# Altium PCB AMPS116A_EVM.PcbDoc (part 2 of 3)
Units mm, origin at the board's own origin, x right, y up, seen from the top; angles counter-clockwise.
Board outline 95 x 85 mm, 4 copper layers (Top Layer, Mid-Layer 1, Mid-Layer 2, Bottom Layer), stack 1.554 mm thick; 252 components, 134 nets, 806 pads, 625 vias.
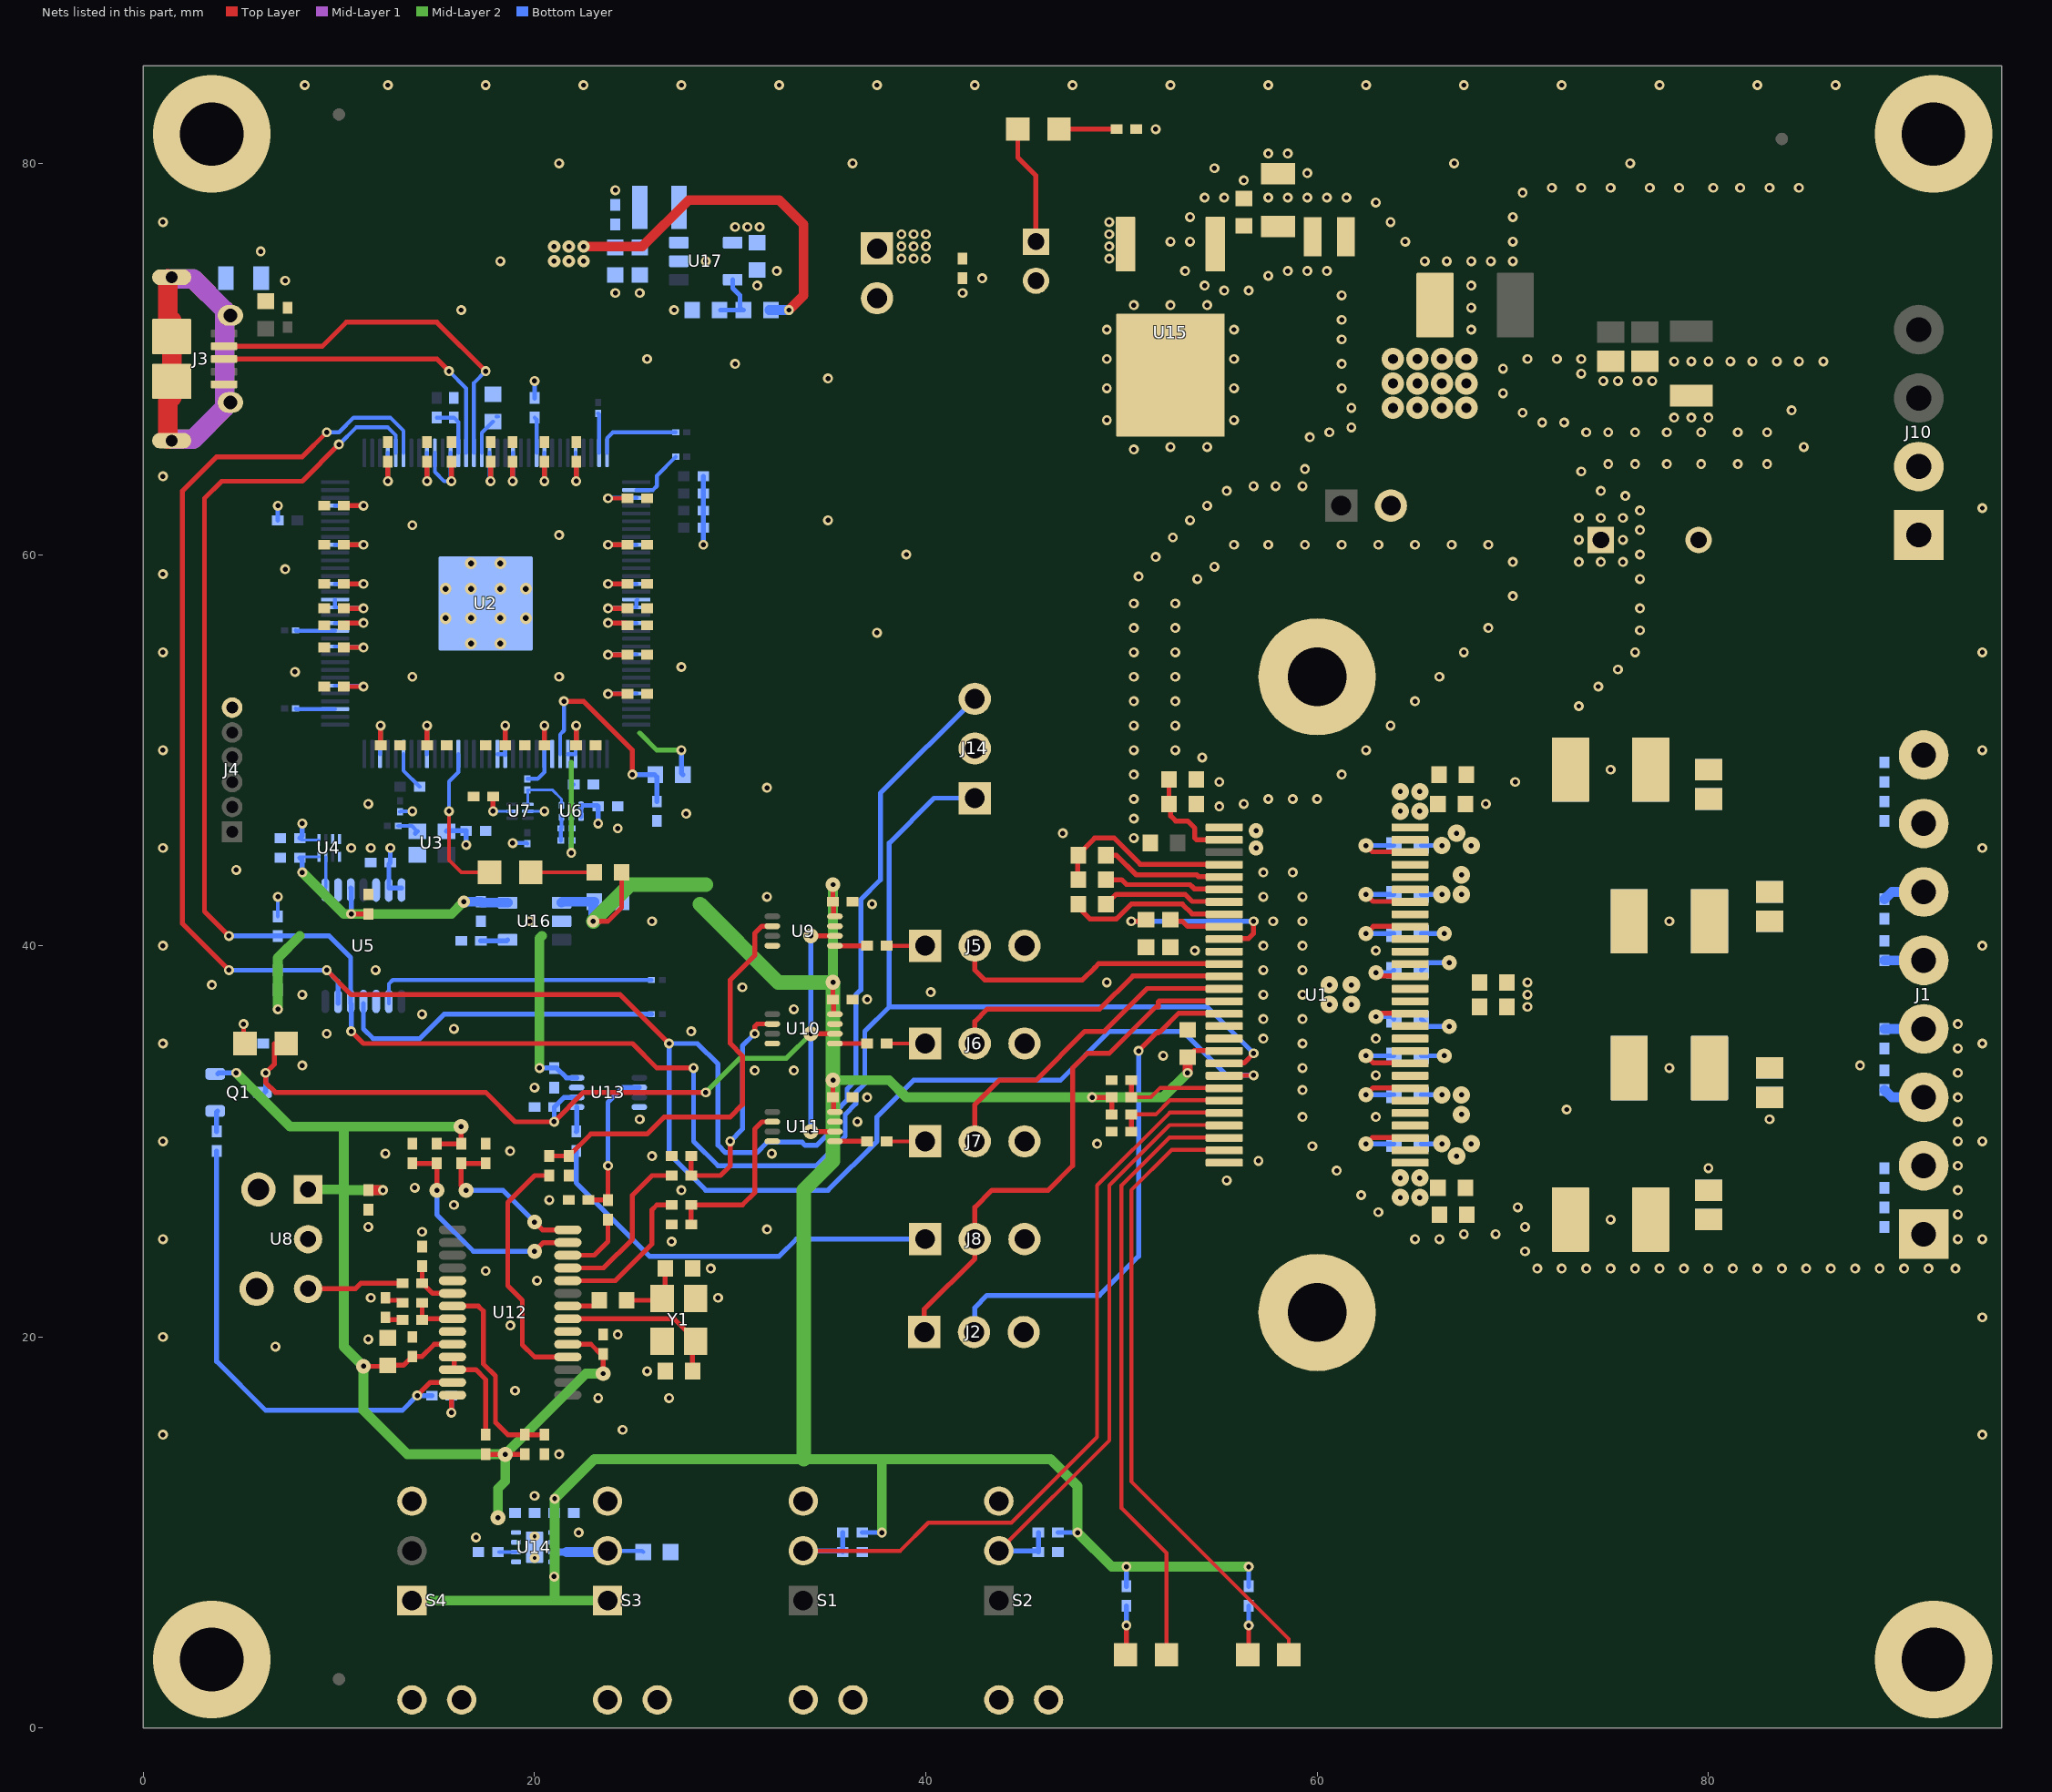
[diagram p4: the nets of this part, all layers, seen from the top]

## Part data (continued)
D2: library part CMP-0002829-3, "LED, Red, SMD", Color=red, Manufacturer=Lite-On, PartNumber=LTST-C170KRKT, Value1=W, Value2=2V
D3 D4: library part CMP-0002889-2, "LED, Blue, SMD", Color=Blue, Manufacturer=Lite-On, PartNumber=LTST-C170TBKT, Value1=W, Value2=3.3V
D5: library part CMP-0002888-2, "LED, Green, SMD", Color=Green, Manufacturer=Lite-On, PartNumber=LTST-C170KGKT, Value1=W, Value2=2V
FID1 FID2 FID3 FID4 FID5 FID6: library part CMP-0077181-1, "Fiducial mark.  There is nothing to buy or mount.", Manufacturer=N/A
H1: library part CMP-0004050-1, "Heat Sink for DKQ Packages, 41.4x20 mm", Manufacturer=Any, PartNumber=HS-DKQ56_20X41.4X32.77
H6 H7 H8 H9: library part CMP-0003665-1, "Standoff, Hex, 12mm, M3, Aluminum", Manufacturer=Keystone, PartNumber=24434, Supplier Part Number 1=36-24434-ND
J1: library part CMP-0075135-1, "Terminal Block, 3.5mm, 8-Pos, TH", Color=Grey, Manufacturer="On-Shore Technology", PartNumber=ED555/8DS, Supplier Part Number 1=ED1520-ND
J2 J5 J6 J7 J8 J14: library part CMP-0002334-1, "Header, 100mil, 3x1, Gold, TH", Manufacturer="Sullins Connector Solutions", PartNumber=PBC03SAAN, Supplier Part Number 1=S1011E-03-ND
J3: library part CMP-0055301-1, "Connector, Receptacle, Micro-USB Type AB, R/A, Bottom Mount SMT", Manufacturer=Molex, Supplier Part Number 1=WM17143CT-ND
J4: library part CMP-0054640-1, "Receptacle, 50mil, 6x1, Gold, R/A, TH", Color=Black, Manufacturer="Sullins Connector Solutions", PartNumber=LPPB061NGCN-RC, Supplier Part Number 1=S9010E-06-ND
J10: library part CMP-0074917-1, "Terminal Block, 3.5mm Pitch, 4x1, TH", Color=Grey, Current_A=6A, Manufacturer="On-Shore Technology", PartNumber=ED555/4DS, Supplier Part Number 1=ED1516-ND, Voltage_V=150V
J12 J13: library part CMP-0054566-1, "Header, 100mil, 2x1, Gold, TH", Color=Black, Current_A=3A, Manufacturer="Sullins Connector Solutions", PartNumber=PBC02SAAN, Supplier Part Number 1=S1011E-02-ND, Voltage_V=1.8kV
L1 L2 L7 L8 L9 L10 L11 L12: library part CMP-0059924-1, "Inductor, 3.3 uH, 4.5 A, 0.038 ohm, AEC-Q200 Grade 0, SMD", Manufacturer=Cyntec, Value1="0.038 ohm", Value2=4.5A, ValueDisplayed=3.3uH
L3: library part CMP-0003428-2, "Ferrite Bead, 30 ohm @ 100 MHz, 6 A, 0805", Manufacturer=TDK, Supplier Part Number 1=445-1566-1-ND, Value1="0.01 ohm", Value2=6A, ValueDisplayed="30 ohm"
L4: library part CMP-0059922-1, "Inductor, 1.5 uH, 5.5 A, 0.017 ohm, AEC-Q200 Grade 0, SMD", Manufacturer=Cyntec, Value1="0.017 ohm", Value2=5.5A, ValueDisplayed=1.5uH
L5: library part CMP-0003430-1, "Ferrite Bead, 180 ohm @ 100 MHz, 3.4 A, 0806", Manufacturer=MuRata, PartNumber=NFZ2MSM181SN10L, Supplier Part Number 1=81-NFZ2MSM181SN10L, Value1="0.025 ohm", Value2=3.4A, ValueDisplayed="180 ohm"
L6: library part CMP-0058752-1, "Inductor, Multilayer, Ferrite, 2.2 uH, 1.3 A, 0.08 ohm, SMD", Manufacturer=MuRata, Supplier Part Number 1=490-5114-1-ND, Value1="0.08 ohm", Value2=1.3A, ValueDisplayed=2.2uH
Logo1: library part CMP-0074838-1, "Texas Instrument Corporate Signature"
Logo2: library part CMP-0074847-1, "FCC_disclaimer"
Logo3: library part CMP-0074769-1
Logo4: library part CMP-0074844-1
Q1: library part CMP-0000326-2, "Transistor, PNP, 40 V, 0.2 A, SOT-23", Manufacturer="Diodes Inc.", Supplier Part Number 1=MMBT3906-FDICT-ND, Value1="0.2 A", Value2=400
R2 R3 R4 R5 R7 R9 R46 R48 R52 R53 R55 R56: library part CMP-0026414-2, "RES, 4.99 k, 1%, 0.063 W, AEC-Q200 Grade 0, 0402", Manufacturer=Vishay-Dale, PartNumber=CRCW04024K99FKED, Power_W=63mW, Supplier Part Number 1=541-4.99KLCT-ND, TempCo="100 ppm/C", Tolerance_%=1%, Value2=0.063W, Value_Code=4k99, ValueDisplayed=4.99k
R6 R8: library part CMP-0026071-3, "RES, 1.00 k, 1%, 0.063 W, AEC-Q200 Grade 0, 0402", Manufacturer=Vishay-Dale, PartNumber=CRCW04021K00FKED, Power_W=63mW, Supplier Part Number 1=541-1.00KLCT-ND, TempCo="100 ppm/C", Tolerance_%=1%, Value2=0.063W, Value_Code=1k00, ValueDisplayed=1.00k
R10: library part CMP-0026657-1, "RES, 1.00 k, 1%, 0.1 W, 0402", Manufacturer=Panasonic, Power_W=100mW, Supplier Part Number 1=P1.00KLCT-ND, TempCo="100 ppm/C", Tolerance_%=1%, Value2=0.1W, Value_Code=1k00, ValueDisplayed=1.00k
R11 R12: library part CMP-0026681-1, "RES, 2.20 k, 1%, 0.1 W, 0402", Manufacturer=Panasonic, Power_W=100mW, Supplier Part Number 1=P2.20KLCT-ND, TempCo="100 ppm/C", Tolerance_%=1%, Value2=0.1W, Value_Code=2k20, ValueDisplayed=2.20k
R13: library part CMP-0023160-5, "RES, 4.75, 1%, 0.1 W, 0603", Manufacturer=Yageo, Power_W=100mW, Supplier Part Number 1=311-4.75HRCT-ND, TempCo="200 ppm/C", Tolerance_%=1%, Value2=0.1W, Value_Code=4R75, ValueDisplayed=4.75
R14 R21 R22 R23 R25 R28 R29 R30: library part CMP-0027614-1, "RES, 33.2, 1%, 0.05 W, 0201", Manufacturer="Yageo America", PartNumber=RC0201FR-0733R2L, Power_W=50mW, Supplier Part Number 1=YAG2608CT-ND, TempCo="200 ppm/C", Tolerance_%=1%, Value2=0.05W, Value_Code=33R2, ValueDisplayed=33.2
R15 R16 R17 R18: library part CMP-0026737-1, "RES, 47.0 k, 1%, 0.0625 W, 0402", Manufacturer="Yageo America", Power_W=62.5mW, Supplier Part Number 1=311-47.0KLRCT-ND, TempCo="100 ppm/C", Tolerance_%=1%, Value2=0.0625W, Value_Code=47k0, ValueDisplayed=47.0k
R19 R24: library part CMP-0078669-1, "RES, 10.0 k, 1%, 0.063 W, 0402", Manufacturer="Yageo America", Power_W=63mW, Supplier Part Number 1=311-10.0KLRCT-ND, TempCo="100 ppm/C", Tolerance_%=1%, Value2=0.063W, Value_Code=10k0, ValueDisplayed=10.0k
R20: library part CMP-0023235-5, "RES, 680, 1%, 0.1 W, 0603", Manufacturer=Yageo, Power_W=100mW, Supplier Part Number 1=311-680HRCT-ND, TempCo="100 ppm/C", Tolerance_%=1%, Value2=0.1W, Value_Code=680R, ValueDisplayed=680
R26: library part CMP-0026659-2, "RES, 100 k, 1%, 0.1 W, 0402", Manufacturer=Panasonic, Power_W=100mW, TempCo="100 ppm/C", Tolerance_%=1%, Value2=0.1W, Value_Code=100k
R27: library part CMP-0023114-5, "RES, 43.2, 1%, 0.1 W, 0603", Manufacturer=Yageo, Power_W=100mW, Supplier Part Number 1=311-43.2HRCT-ND, TempCo="100 ppm/C", Tolerance_%=1%, Value2=0.1W, Value_Code=43R2, ValueDisplayed=43.2
R31: library part CMP-0027523-1, "RES, 25.5 k, 1%, 0.05 W, 0201", Manufacturer="Yageo America", PartNumber=RC0201FR-0725K5L, Power_W=50mW, Supplier Part Number 1=YAG2538CT-ND, TempCo="200 ppm/C", Tolerance_%=1%, Value2=0.05W, Value_Code=25k5, ValueDisplayed=25.5k
R32 R33 R34: library part CMP-0027301-2, "RES, 10.2 k, 1%, 0.05 W, 0201", Manufacturer="Yageo America", Power_W=50mW, Supplier Part Number 1=311-10.2KMCT-ND, TempCo="200 ppm/C", Tolerance_%=1%, Value2=0.05W, Value_Code=10k2, ValueDisplayed=10.2k
R35: library part CMP-0027757-1, "RES, 51.0 k, 1%, 0.05 W, 0201", Manufacturer="Yageo America", PartNumber=RC0201FR-0751KL, Power_W=50mW, Supplier Part Number 1=311-51.0KMCT-ND, TempCo="200 ppm/C", Tolerance_%=1%, Value2=0.05W, Value_Code=51k0, ValueDisplayed=51.0k
R36: library part CMP-0026992-3, "RES, 0, 5%, 0.1 W, AEC-Q200 Grade 0, 0402", Manufacturer=Panasonic, Power_W=100mW, Supplier Part Number 1=P0.0JCT-ND, TempCo="600 ppm/C", Tolerance_%=5%, Value2=0.1W, Value_Code=0000, ValueDisplayed=0
R37 R38 R39 R40 R41 R42 R44 R45 R49: library part CMP-0026404-2, "RES, 49.9, 1%, 0.063 W, AEC-Q200 Grade 0, 0402", Manufacturer=Vishay-Dale, PartNumber=CRCW040249R9FKED, Power_W=63mW, Supplier Part Number 1=541-49.9LCT-ND, TempCo="100 ppm/C", Tolerance_%=1%, Value2=0.063W, Value_Code=49R9, ValueDisplayed=49.9
R43: library part CMP-0023129-5, "RES, 470, 1%, 0.1 W, 0603", Manufacturer=Yageo, PartNumber=RC0603FR-07470RL, Power_W=100mW, Supplier Part Number 1=311-470HRCT-ND, TempCo="100 ppm/C", Tolerance_%=1%, Value2=0.1W, Value_Code=470R, ValueDisplayed=470
R47: library part CMP-0026656-1, "RES, 100, 1%, 0.1 W, 0402", Manufacturer=Panasonic, PartNumber=ERJ-2RKF1000X, Power_W=100mW, Supplier Part Number 1=P100LCT-ND, TempCo="100 ppm/C", Tolerance_%=1%, Value2=0.1W, Value_Code=100R, ValueDisplayed=100
R50: library part CMP-0026505-2, "RES, 681, 1%, 0.063 W, AEC-Q200 Grade 0, 0402", Manufacturer=Vishay-Dale, PartNumber=CRCW0402681RFKED, Power_W=63mW, Supplier Part Number 1=541-681LCT-ND, TempCo="100 ppm/C", Tolerance_%=1%, Value2=0.063W, Value_Code=681R, ValueDisplayed=681
R51: library part CMP-0025950-3, "RES, 100 k, 1%, 0.063 W, AEC-Q200 Grade 0, 0402", Manufacturer=Vishay-Dale, PartNumber=CRCW0402100KFKED, Power_W=63mW, Supplier Part Number 1=541-100KLCT-ND, TempCo="100 ppm/C", Tolerance_%=1%, Value2=0.063W, Value_Code=100k
R54: library part CMP-0025958-3, "RES, 10.0 k, 1%, 0.063 W, AEC-Q200 Grade 0, 0402", Manufacturer=Vishay-Dale, PartNumber=CRCW040210K0FKED, Power_W=63mW, Supplier Part Number 1=541-10.0KLCT-ND, TempCo="100 ppm/C", Tolerance_%=1%, Value2=0.063W, Value_Code=10k0, ValueDisplayed=10.0k
R57 R58: library part CMP-0026910-3, "RES, 360, 5%, 0.063 W, AEC-Q200 Grade 0, 0402", Manufacturer=Vishay-Dale, PartNumber=CRCW0402360RJNED, Power_W=63mW, Supplier Part Number 1=541-360JCT-ND, TempCo="200 ppm/C", Tolerance_%=5%, Value2=0.063W, Value_Code=360R, ValueDisplayed=360
R59: library part CMP-0023232-5, "RES, 66.5 k, 1%, 0.1 W, 0603", Manufacturer=Yageo, Power_W=100mW, Supplier Part Number 1=311-66.5KHRCT-ND, TempCo="100 ppm/C", Tolerance_%=1%, Value2=0.1W, Value_Code=66k5, ValueDisplayed=66.5k
R61: library part CMP-0022735-5, "RES, 100 k, 1%, 0.1 W, 0603", Manufacturer=Yageo, Power_W=100mW, Supplier Part Number 1=311-100KHRCT-ND, TempCo="100 ppm/C", Tolerance_%=1%, Value2=0.1W, Value_Code=100k
S1 S2 S3 S4: library part CMP-0002268-2, "Switch, SPDT, On-On, 1 Pos, 0.4A, 28 VDC, TH", CurrentRating_mA=400A, Manufacturer="Copal Electronics", PartNumber=FT1D-4M-Z, Supplier Part Number 1=563-1143-ND
SH1 SH2 SH3 SH4 SH5 SH6: library part CMP-0003623-3, "Shunt, 100mil, Gold plated, Black", Alternate Manufacturer=3M, Alternate PartNumber=969102-0000-DA, Manufacturer=Samtec, Supplier Part Number 1=SAM8858-ND
U1: library part CMP-0089860-1, "45-W, 2-MHz Digital Input 4-Channel Automotive Class-D Audio Amplifier with Load Dump Protection and I 2C Diagnostics", Manufacturer="Texas Instruments", Max Supply Voltage=18V, Min Supply Voltage=3V, Operating Temperature Range="-40°C to +125°C", Output Current Per Channel=6.5A, Power At Speaker R="45W @ 4O"
U2: library part CMP-0004936-1, "IC MCU 512KB RAM, 128TQFP", Manufacturer="XMOS semiconductor", Supplier Part Number 1=880-1100-ND
U3: library part CMP-0006105-3, "OSC, 24 MHz, 2.25 - 3.63 V, SMD", Frequency_Fixed=24MHz, Frequency Stability=+/-20ppm, Manufacturer="Abracon Corporation", PartNumber=ASTMLPA-24.000MHZ-EJ-E-T, Supplier Part Number 1=535-13061-1-ND
U4: library part CMP-0050935-3, "Dual-Bit Dual-Supply Bus Transceiver, DQE0008A, LARGE T&R", F @ Nom Voltage(Max)(Mhz)=100, Generic Part Number=SN74AVC2T244, ICC @ Nom Voltage(Max)(mA)=0.0009, Manufacturer="Texas Instruments", Operating Temperature Range(C)="-40 to 85", Rating=Catalog, tpd @ Nom Voltage(Max)(ns)=20,7,3.5, Voltage(Nom)(V)=0.9,1.2,1.5,1.8,2.5,3.3
U5: library part CMP-0065668-3, "Programmable 1-PLL VCXO Clock Synthesizer with 2.5-V or 3.3-V LVCMOS Outputs, PW0014A (TSSOP-14)", Alternate Manufacturer="Texas Instruments", Alternate PartNumber=CDCE913PW, Operating Temperature Range="-40 to 85 C", Rating=Catalog
U6: library part CMP-0032427-3, "Single-Channel Ultra-Small Adjustable Supervisory Circuit With Active-High Open-Drain Output, DRY0006A (USON-6)", Manufacturer="Texas Instruments", Operating Temperature Range="-40 to 125 C", Rating=Catalog, Threshold Voltage 1 (typ)(Typ)(V)=Adjustable
U7: library part CMP-0051795-5, "Enhanced Product Dual Buffer/Driver with Open-Drain Output, DCK0006A (SOT-SC70-6)", F @ Nom Voltage(Max)(Mhz)=150, Generic Part Number=SN74LVC2G07, ICC @ Nom Voltage(Max)(mA)=0.01, Manufacturer="Texas Instruments", Operating Temperature Range(C)="-40 to 125", Rating=Catalog, tpd @ Nom Voltage(Max)(ns)=8.6,4.4,3.7,2.9, Voltage(Nom)(V)=1.8,2.5,3.3,5
U8: library part CMP-0004896-1, "Photolink- Fiber Optic Receiver, TH", Manufacturer=Everlight, PartNumber=PLR135/T10, Supplier Part Number 1=1080-1433-ND
U9 U10 U11 U13: library part CMP-0051026-2, "Single 2-Line to 1-Line Data Selector/Multiplexer, DCU0008A, LARGE T&R", Alternate Manufacturer="Texas Instruments", Alternate PartNumber=SN74LVC2G157DCUT, F @ Nom Voltage(Max)(Mhz)=150, Generic Part Number=SN74LVC2G157, ICC @ Nom Voltage(Max)(mA)=0.01, Operating Temperature Range(C)="-40 to 85", PartNumber=SN74LVC2G157DCUR, Rating=Catalog, tpd @ Nom Voltage(Max)(ns)=14,8,6,4, Voltage(Nom)(V)=1.8,2.5,3.3,5
U12: library part CMP-0028713-1, "Automotive Catalog 96-kHz 24-Bit Digital Audio Interface Receiver, 50 ps Jitter, 3.3V, -40 to 85 degC, 28-Pin TSSOP (PW), Green (RoHS & no Sb/Br)", Manufacturer="Texas Instruments", PartNumber=DIR9001IPWQ1, Supply Voltage(s)(V)=3.3
U14: library part CMP-0073678-3, "5.5V, 4A, 16mO Automotive Load Switch With Adjustable Rise Time and Optional Quick Output Discharge, DSG0008B (WSON-8)", Alternate Manufacturer="Texas Instruments", Alternate PartNumber=TPS22965TDSGTQ1, PartNumber=TPS22965TDSGRQ1
U15: library part CMP-0036772-2, "Single Output Automotive LDO, 500 mA, Fixed 3.3 V Output, 3.8 to 26 V Input, 3-pin PFM (KVU), -40 to 125 degC, Green (RoHS & no Sb/Br)", Manufacturer="Texas Instruments", PartNumber=TL760M33QKVURQ1, Rating=Automotive
U16: library part CMP-0036854-2, "Single Output LDO, 400mA, Adj.(1.2 to 5.5V), Cap free, Low Noise, Reverse Current Protection, DBV0005A (SOT-23-5)", Manufacturer="Texas Instruments", PartNumber=TPS73618DBVR, Rating=Catalog
U17: library part CMP-0013046-2, "1-A High Efficiency Step-Down Converter in SOT23-5 Package, DBV005A, DBV0005A (SOT-5)", Alternate Manufacturer="Texas Instruments", Alternate PartNumber=TLV62568DBVT
Y1: library part CMP-0004595-3, "Crystal, 12.288 MHz, 18pF, SMD", Frequency_Fixed=12.288MHz, Frequency Stability=+/-30ppm, Manufacturer="Abracon Corporation", PartNumber=ABM8G-12.288MHZ-18-D2Y-T, Supplier Part Number 1=535-10262-1-ND
ZZ1: library part CMP-0077236-1
ZZ2: library part CMP-0077237-1
ZZ3: library part CMP-0077238-1
ZZ4 ZZ5: library part CMP-0003615-1

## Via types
v1: diameter 0.508, hole 0.254, Top Layer to Bottom Layer, tented both sides, 516 vias
v2: diameter 0.762, hole 0.254, Top Layer to Bottom Layer, tented both sides, 30 vias
v3: diameter 1.143, hole 0.508, Top Layer to Bottom Layer, tented both sides, 28 vias
v4: diameter 0.889, hole 0.254, Top Layer to Bottom Layer, tented both sides, 24 vias
v5: diameter 0.6, hole 0.3, Top Layer to Bottom Layer, 12 vias
v6: diameter 0.635, hole 0.254, Top Layer to Bottom Layer, tented both sides, 9 vias
v7: diameter 6, hole 3.25, Top Layer to Bottom Layer, 4 vias
v8: diameter 0.5, hole 0.2, Top Layer to Bottom Layer, 2 vias

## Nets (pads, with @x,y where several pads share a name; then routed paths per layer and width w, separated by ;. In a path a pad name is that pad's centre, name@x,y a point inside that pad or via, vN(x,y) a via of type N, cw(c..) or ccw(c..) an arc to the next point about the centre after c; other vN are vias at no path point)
1.0V: C19.2 C20.2 C21.2 C22.2 C23.2 C29.2 C30.2 C31.2 C32.2 C33.2 C40.2 C41.2 C42.2 C43.2 C90.1 C91.1 C103.1 L6.2 R13.1 R31.1 R59.2 U2.11 U2.16 U2.17 U2.24 U2.36 U2.41 U2.49 U2.56 U2.60 U2.73 U2.80 U2.81 U2.87 U2.101 U2.102 U2.120 U2.126 | length 76.4
  Top Layer w0.25: C32.2@10.25,55.25 v1(11.25,55.25) ; C43.2@10.25,57.25 v1(11.25,57.25) ; C31.2@10.25,60.5 v1(11.25,60.5) ; C33.2@12.125,50.25 v1(12.125,51.25) ; v1(12.5,63.75) C29.2@12.5,64.75 ; C19.2@14.5,50.25 v1(14.5,51.25) ; v1(14.5,63.75) C40.2@14.5,64.75 ; v1(17.75,63.75) C41.2@17.75,64.75 ; v1(20.5,63.75) C42.2@20.5,64.75 ; C20.2@22.125,50.25 v1(22.125,51.25) ; v1(22.125,63.75) C30.2@22.125,64.75 ; v1(23.75,54.875) C21.2@24.75,54.875 ; v1(23.75,57.25) C22.2@24.75,57.25 ; v1(23.75,60.5) C23.2@24.75,60.5
  Top Layer w0.5: v6(22.5,75.75) 25.5,75.75 27.875,78.125 32.5,78.125 33.75,76.875 33.75,73.25 v1(33,72.5)
  Mid-Layer 2 w0.25: 10.25,55.25 v1(11.25,55.25) ; 10.25,57.25 v1(11.25,57.25) ; 10.25,60.5 v1(11.25,60.5) ; 12.125,50.5 v1@12.125,51.125 ; v1(12.5,63.75) 12.5,64.75 ; 14.5,50.25 v1(14.5,51.25) ; v1(14.5,63.75) 14.5,64.75 ; v1(17.75,63.75) 17.75,64.75 ; v1(20.5,63.75) 20.5,64.75 ; v1(21.875,44.75) 21.875,49.375 ; 22.125,50.25 v1(22.125,51.25) ; v1(22.125,63.75) 22.125,64.75 ; v1(23.75,54.875) 24.75,54.875 ; v1(23.75,57.25) 24.75,57.25 ; v1(23.75,60.5) 24.75,60.5 ; 25.375,50.875 26.25,50 v1(27.5,50)
  Bottom Layer w0.2: U2.11@9.8,55.3 v1@11.2,55.3 ; U2.17@9.8,57.7 U2.16@9.8,57.3 v1@11.2,57.3 ; U2.24@9.8,60.5 v1(11.25,60.5) ; U2.126@12.1,49.8 v1@12.1,51.225 ; v1(12.5,63.75) U2.36@12.5,65.2 ; U2.120@14.5,49.8 v1(14.5,51.25) ; v1(14.5,63.75) U2.41@14.5,65.2 ; v1@17.7,63.825 U2.49@17.7,65.2 ; v1(20.5,63.75) U2.56@20.5,65.2 ; U2.102@21.7,49.8 22.025,49.8 U2.101@22.1,49.875 ; U2.101@22.1,49.8 U2.101@22.1,49.875 ; v1@22.1,51.225 U2.101@22.1,49.875 ; v1@22.1,63.775 U2.60@22.1,65.2 ; v1@23.675,57.3 U2.81@25.2,57.3 25.2,57.65 U2.80@25.25,57.7 ; v1(23.75,60.5) U2.73@25.2,60.5 ; v1@23.775,54.9 U2.87@25.2,54.9
  Bottom Layer w0.25: v1(21.875,44.75) 21.875,45.345 R31.1@21.905,45.375 ; v1(27.5,50) 27.5,48.825 R13.1@27.575,48.75
  Bottom Layer w0.5: R59.2@32,72.5 v1(33,72.5)
  other v6: 21,75 21.75,75 22.5,75 21,75.75 21.75,75.75
1.8V: C54.1 C55.1 C88.2 U4.8 U5.3 U16.5 | length 15.7
  Top Layer w0.25: v1(10.625,41.625) C55.1@11.5,41.625
  Mid-Layer 2 w0.5: v1(8.125,43.75) 10.25,41.625 v1(10.625,41.625) 15.75,41.625 v6(16.375,42.25)
  Bottom Layer w0.15: C54.1@8,44.5 8.05,44.55 U4.8@8.975,44.55
  Bottom Layer w0.25: C54.1@8,44.5 8.125,44.375 v1(8.125,43.75) ; U5.3@10.6,42.95 10.625,42.925 v1(10.625,41.625)
  Bottom Layer w0.5: v6(16.375,42.25) C88.2@17.25,42.25 17.3,42.2 U16.5@18.625,42.2
3.3V: C1.2 C24.1 C25.1 C26.1 C27.1 C28.1 C34.1 C35.1 C36.1 C37.1 C38.1 C44.1 C45.1 C49.1 C50.1 C51.1 C52.1 C53.1 C73.2 C74.2 C75.2 C76.2 C77.2 C85.2 C86.1 C87.2 C89.1 D5.1 J12.1 R2.2 R4.2 R6.1 R7.2 R8.1 R9.2 R10.1 R11.1 R12.1 R15.2 R16.2 R17.2 R18.2 R19.2 R20.1 R32.1 R33.1 R34.1 S3.1 S4.1 U1.19 U2.6 U2.14 U2.19 U2.29 U2.42 U2.44 U2.52 U2.67 U2.78 U2.83 U2.92 U2.105 U2.110 U2.111 U3.4 U4.1 U5.6 U5.7 U6.1 U6.6 U7.5 U9.8 U10.8 U11.8 U13.8 U14.1 U14.2 U14.4 U15.3 U16.1 U17.4 | length 214.3
  Top Layer w0.2: v1(23.75,62.875) C44.1@24.75,62.875
  Top Layer w0.25: C34.1@10.25,56.375 10.375,56.5 v1(11.25,56.5) ; C35.1@10.25,58.5 v1(11.25,58.5) ; C36.1@10.25,62.5 v1(11.25,62.5) ; C73.2@10.375,53.25 v1(11.25,53.25) ; v1(15.75,63.75) C37.1@15.75,64.625 ; v1(17.875,46.875) C25.1@17.875,47.625 ; C51.1@18.5,50.25 v1(18.5,51.25) ; v1(18.875,63.75) C38.1@18.875,64.75 ; C50.1@20.5,50.25 v1(20.5,51.25) ; v6(23,41.25) 23.75,41.25 24.45,41.95 R20.1@24.45,43.75 ; v1(23.75,52.875) C52.1@24.75,52.875 ; v1(23.75,56.5) 24.625,56.5 C53.1@24.75,56.375 ; v1(23.75,58.5) C45.1@24.75,58.5 ; C76.2@35.25,32.25 v2(35.25,33.125) ; C75.2@35.25,37.25 v2(35.25,38.125) ; C74.2@35.25,42.25 v2(35.25,43.125) ; U11.8@35.275,31.5 C76.2@35.275,32.225 ; U10.8@35.275,36.5 C75.2@35.275,37.225 ; U9.8@35.275,41.5 C74.2@35.275,42.225 ; D5.1@44.7,81.75 44.7,80.3 45.625,79.375 C86.1@45.625,76 ; C1.2@53.375,34.3 53.718,34.643 U1.19@55.25,34.643
  Top Layer w0.254: v1(48.5,32.25) R2.2@49.5,32.25 R4.2@49.5,31.375
  Top Layer w0.5: v1(53.375,33.5) C1.2@53.375,34.3 C1.2@53.375,34.375
  Mid-Layer 2 w0.5: v1(6.875,36.75) 6.875,39.375 8,40.5 ; S4.1@13.73,6.525 21,6.525 ; v1(20.25,33.75) 20.25,40.375 20.375,40.5 ; S3.1@23.73,6.525 21,6.525 ; v2(35.25,33.125) 38.125,33.125 39,32.25 v1(48.5,32.25) 52.125,32.25 v1(53.375,33.5) ; v2(35.25,38.125) v2(35.25,43.125) ; 37.625,13.75 46.25,13.75 ; v1(37.75,10) 37.75,13.75 33.75,13.75 23.05,13.75 v1(21.025,11.725) 21.025,6.55 21,6.525 ; 46.375,13.75 47.75,12.375 v1(47.75,10) 49.5,8.25 v1(50.25,8.25) v1(56.5,8.25)
  Mid-Layer 2 w0.75: v6(23,41.25) 24.875,43.125 28.75,43.125 ; 28.45,42.125 32.45,38.125 v2(35.25,38.125) v2(35.25,33.125) 35.25,29 33.75,27.5 33.75,13.75
  Bottom Layer w0.15: C24.1@8,45.5 8.1,45.4 U4.1@8.975,45.4 ; v1(17.875,46.875) U7.5@18.85,46.875
  Bottom Layer w0.2: v1(6.875,36.75) R12.1@6.875,37.75 ; R11.1@6.875,41.5 v1(6.875,42.5) ; U2.6@9.8,53.3 v1@11.2,53.3 ; U2.14@9.8,56.5 v1(11.25,56.5) ; U2.19@9.8,58.5 v1(11.25,58.5) ; U2.29@9.8,62.5 v1(11.25,62.5) ; R33.1@13.125,46.845 13.155,46.875 v1(13.75,46.875) ; U2.42@14.9,65.2 14.9,64.225 15.375,63.75 v1(15.75,63.75) ; v1@15.7,63.8 U2.44@15.7,65.2 ; U2.111@18.1,49.8 18.45,49.8 U2.110@18.5,49.75 ; U2.110@18.5,49.8 v1(18.5,51.25) ; v1(18.875,45.25) 19.595,45.25 R34.1@19.625,45.22 ; v1@18.9,63.775 U2.52@18.9,65.2 ; R32.1@19.625,48.53 20.155,48.53 20.5,48.875 U2.105@20.5,49.8 v1(20.5,51.25) ; v1(23.75,56.5) U2.83@25.2,56.5 ; v1(23.75,58.5) U2.78@25.2,58.5 ; v1@23.775,52.9 U2.92@25.2,52.9 ; v1@23.775,62.9 U2.67@25.2,62.9
  Bottom Layer w0.25: R10.1@6.875,61.75 v1(6.875,62.5) ; C24.1@8,45.5 8.125,45.625 v1(8.125,46.25) ; v1(12.625,45) C28.1@12.625,44.25 12.55,44.175 12.55,42.95 U5.7@13.2,42.95 ; U3.4@15.5,45.85 15.525,45.875 C49.1@16.5,45.875 v1(16.5,45.155) ; R19.2@20,68 v1(20,68.875) ; v1(20.25,33.75) C27.1@21,33.75 21.125,33.75 21.625,33.25 U13.8@22.15,33.25 ; U6.1@22.375,46.6 U6.6@22.375,47.175 23.2,47.175 C26.1@23.25,47.125 v1(23.25,46.25) ; v1(28.625,60.5) R18.2@28.625,61.375 R17.2@28.625,62.25 R16.2@28.625,63.125 R15.2@28.625,64 ; R6.1@36.75,10 v1(37.75,10) ; R8.1@46.75,10 v1(47.75,10) ; R9.2@50.25,7.25 v1(50.25,8.25) ; R7.2@56.5,7.25 v1(56.5,8.25)
  Bottom Layer w0.5: U16.1@21.375,42.2 21.425,42.25 C87.2@23.05,42.25 23,42.2 v6(23,41.25)
  other v1: 21,7.75 38.75,75.125 39.375,75.125 40,75.125 49.375,75.125 38.75,75.75 39.375,75.75 40,75.75 49.375,75.75 38.75,76.375 39.375,76.375 40,76.375 49.375,76.375 30.25,76.75 30.875,76.75 31.5,76.75 49.375,77
3.3V-SPDIF: C56.1 C65.1 C66.2 C67.2 C70.1 Q1.2 R46.2 R51.2 R53.1 R56.1 U8.1 U12.5 U12.24 U14.7 U14.8 | length 63.9
  Top Layer w0.25: v2(11.25,18.5) 12.45,18.5 C65.1@12.5,18.55 13.3,18.55 C66.2@13.75,19 14.25,19 14.875,19.625 U12.24@15.9,19.625 ; U12.5@21.6,19.625 22.875,19.625 23.375,19.125 C67.2@23.5,19.125 v2(23.5,18.125)
  Top Layer w0.254: R53.1@15,29.875 R56.1@16.25,29.875 v2(16.25,30.75) ; R46.2@17.5,14 v2(18.5,14) R51.2@19.5,14
  Top Layer w0.5: C56.1@11.5,27.5 v1(12.25,27.5)
  Mid-Layer 2 w0.5: v1(4.75,33.5) 7.5,30.75 10.25,30.75 ; U8.1@8.42,27.54 10.21,27.54 10.25,27.5 ; v1(12.25,27.5) 10.25,27.5 ; v2(16.25,30.75) 10.25,30.75 ; v2@18.25,10.75 v2(18.125,10.75) 18.125,12.25 18.5,12.625 v2(18.5,14) ; v2(23.5,18.125) 22.625,18.125 v2(18.5,14) ; 10.25,27.5 10.25,19.5 v2(11.25,18.5) 11.25,16.25 13.5,14 v2(18.5,14) ; 10.25,27.5 10.25,30.75
  Bottom Layer w0.25: Q1.2@3.8,33.45 3.85,33.5 v1(4.75,33.5)
\FAULT: D2.2 U1.26 | length 31.2
  Top Layer w0.2: D2.2@52.3,3.75 52.3,8.95 50,11.25 50,27.75 52.447,30.197 U1.26@55.25,30.197
\MUTE: C18.1 R8.2 S2.2 U1.25 | length 31.2
  Top Layer w0.2: S2.2@43.73,9.065 49.375,14.71 49.375,27.75 52.457,30.832 U1.25@55.25,30.832
  Bottom Layer w0.25: S2.2@43.73,9.065 45.685,9.065 C18.1@45.75,9 R8.2@45.75,10
\STANDBY: C17.1 R6.2 S1.2 U1.24 | length 41.4
  Top Layer w0.2: S1.2@33.73,9.065 38.69,9.065 40.125,10.5 44.375,10.5 48.75,14.875 48.75,27.75 52.467,31.467 U1.24@55.25,31.467
  Bottom Layer w0.25: S1.2@33.73,9.065 35.685,9.065 C17.1@35.75,9 R6.2@35.75,10
\WARN: D1.2 U1.27 | length 32.7
  Top Layer w0.2: U1.27@55.25,29.562 52.562,29.562 50.5,27.5 50.5,12.605 58.55,4.555 D1.2@58.55,3.75
AREF: C10.1 C96.1 U1.4 | length 9.8
  Top Layer w0.254: C10.1@47.75,43.25 47.75,44.625 48.625,45.5 49.625,45.5 50.957,44.168 U1.4@55.237,44.168
AVSS: C12.1 U1.7 | length 6.4
  Top Layer w0.254: C12.1@49.2,42.125 49.237,42.125 49.737,42.625 53.25,42.625 53.612,42.263 U1.7@55.25,42.263
BST1+: C106.1 U1.35 | length 3.9
  Top Layer w0.25: v2(62.5,32.375) 62.863,32.738 64.762,32.738 U1.35@64.775,32.75
  Bottom Layer w0.25: v2(62.5,32.375) C106.1@63.925,32.375
BST1-: C107.1 U1.31 | length 3.8
  Top Layer w0.25: v2(62.5,29.875) 62.823,30.198 U1.31@64.762,30.198
  Bottom Layer w0.25: v2(62.5,29.875) C107.1@63.925,29.875
BST2+: C104.1 U1.41 | length 2.8
  Top Layer w0.25: v2(63,36.375) 63.173,36.548 U1.41@64.762,36.548
  Bottom Layer w0.25: v2(63,36.375) 63.8,36.375 C104.1@63.925,36.25
BST2-: C105.1 U1.37 | length 3.8
  Top Layer w0.25: v2(62.5,34.375) 62.867,34.008 U1.37@64.762,34.008
  Bottom Layer w0.25: v2(62.5,34.375) C105.1@63.925,34.375
BST3+: C97.1 U1.48 | length 3.8
  Top Layer w0.25: v2(62.5,40.625) 62.867,40.993 U1.48@64.762,40.993
  Bottom Layer w0.25: v2(62.5,40.625) C97.1@63.925,40.625
BST3-: C98.1 U1.44 | length 2.8
  Top Layer w0.25: v2(63,38.625) 63.173,38.453 U1.44@64.762,38.453
  Bottom Layer w0.25: v2(63,38.625) 63.8,38.625 C98.1@63.925,38.75
BST4+: C6.1 U1.54 | length 3.8
  Top Layer w0.25: v2(62.5,45.125) 62.823,44.803 U1.54@64.762,44.803
  Bottom Layer w0.25: v2(62.5,45.125) C6.1@63.925,45.125
BST4-: C9.1 U1.50 | length 3.9
  Top Layer w0.25: v2(62.5,42.625) 62.863,42.263 64.762,42.263 U1.50@64.775,42.25
  Bottom Layer w0.25: v2(62.5,42.625) C9.1@63.925,42.625
FSYNC: J7.2 U1.14 | length 17.1
  Top Layer w0.25: J7.2@42.5,30 42.5,31.875 43.75,33.125 45.625,33.125 48.125,35.625 49.125,35.625 51.317,37.818 U1.14@55.25,37.818
GND: C1.1 C2.2 C3.1 C4.2 C5.1 C7.2 C8.1 C11.1 C13.2 C14.1 C15.1 C16.1 C17.2 C18.2 C19.1 C20.1 C21.1 C22.1 C23.1 C24.2 C25.2 C26.2 C27.2 C28.2 C29.1 C30.1 C31.1 C32.1 C33.1 C34.2 C35.2 C36.2 C37.2 C38.2 C39.2 C40.1 C41.1 C42.1 C43.1 C44.2 C45.2 C46.2 C47.2 C48.2 C49.2 C50.2 C51.2 C52.2 C53.2 C54.2 C55.2 C56.2 C57.2 C58.2 C59.2 C60.2 C61.2 C62.2 C63.2 C64.2 C65.2 C66.1 C67.1 C68.2 C69.2 C70.2 C71.1 C72.2 C73.1 C74.1 C75.1 C76.1 C77.1 C78.1 C79.1 C80.2 C81.2 C82.1 C83.2 C84.1 C85.1 C86.2 C87.1 C88.1 C89.2 C90.2 C91.2 C92.1 C93.1 C94.2 C95.1 C99.2 C100.1 C101.2 C102.1 C103.2 C108.2 C109.1 C110.2 C111.1 C112.2 C113.1 C114.2 C115.1 H1.1 H1.2 J2.3 J4.6 J5.3 J6.3 J7.3 J8.3 J10.1 J10.2 J12.2 J14.2 L3.2 R3.1 R5.1 R26.1 R27.1 R35.2 R52.2 R54.1 R55.2 R57.1 R58.2 R61.1 S1.3 S1.4 S1.5 S2.3 S2.4 S2.5 S3.3 S3.4 S3.5 S4.3 S4.4 S4.5 U1.1 U1.11 U1.17 U1.18 U1.28 U1.33 U1.36 U1.39 U1.46 U1.49 U1.52 U2.104 U2.129 U3.2 U4.3 U4.4 U4.5 U5.2 U5.5 U5.10 U6.2 U7.2 U8.2 U8.4 U8.5 U9.4 U9.7 U10.4 U10.7 U11.4 U11.7 U12.6 U12.19 U12.23 U13.4 U13.7 U14.5 U14.9 U15.4@52.5,69.17 U16.2 U17.2 Y1.2 Y1.4 | length 2.4
  Top Layer w0.25: C69.2@12.375,22 12.5,21.875 13.125,21.875 C68.2@13.25,21.75
  Bottom Layer w0.15: U7.2@19.65,46.875 v1(20.5,46.875)
  Bottom Layer w0.2: U6.2@21.875,46.575 21.875,46.03 R35.2@21.905,46
  other v1: 17,9.75 22.25,10 20,11.875 21.25,14 1,15 94,15 24.5,15.25 23.25,16.875 26.875,16.875 19,17.25 25.75,18.25 6.75,19.5 11.5,19.875 1,20 24.25,20.125 18.759,20.59 94,21 11.625,22 29.375,22 20.125,22.875 17.5,23.375 29,23.5 71.25,23.5 72.5,23.5 73.75,23.5 75,23.5 76.25,23.5 77.5,23.5 78.75,23.5 80,23.5 81.25,23.5 82.5,23.5 83.75,23.5 85,23.5 86.25,23.5 87.5,23.5 88.75,23.5 90,23.5 91.25,23.5 92.625,23.5 70.625,24.375 27,24.875 1,25 65,25 66.25,25 92.75,25 94,25 67.5,25.25 69.125,25.25 14.25,25.375 31.875,25.5 11.5,25.625 70.625,25.625 75,26 92.75,26.25 63.125,26.375 70.25,26.625 15.875,26.75 20.75,27 62.25,27.25 27.5,27.5 92.75,27.5 13.875,27.625 55.375,28 61,28.5 80,28.625 92.75,28.75 57,29 26,29.25 12.375,29.375 32.125,29.375 18.75,29.5 59.75,29.75 48.75,29.875 1,30 92.75,30 94,30 36.5,31 92.75,31 25.375,31.125 83.125,31.125 59.25,31.25 63,31.25 72.75,31.625 37,32.25 92.75,32.25 59.25,32.625 20,32.75 63,33.375 92.75,33.5 31.25,33.625 33.25,33.625 59.25,33.75 78,33.75 8.125,33.875 87.75,33.875 52.125,34.375 92.75,34.75 1,35 59.25,35 94,35 57.25,35.25 63,35.25 9.375,35.5 28,35.625 15.875,35.75 92.75,36 57.25,36.25 59.25,36.25 14.25,36.5 33.25,36.75 70.75,36.875 37,37.25 8.125,37.5 57.25,37.5 59.25,37.5 70.75,37.5 40.25,37.625 30.625,37.875 3.5,38 49.25,38.125 70.75,38.125 11.875,38.75 57.25,38.75 59.25,38.75 53.75,39.75 63,39.75 1,40 57.25,40 59.25,40 94,40 19.75,41.25 26,41.25 57.75,41.25 59.25,41.25 78,41.25 37.25,42.125 31.875,42.5 57.25,42.5 59.25,42.5 57.25,43.75 58.75,43.75 4.75,43.875 1,45 10.625,45 11.625,45 94,45 50.625,45.5 47,45.75 24.25,46 50.625,46.5 27.75,46.75 55,47.125 11.5,47.25 56.25,47.25 68.625,47.25 50.625,47.5 57.5,47.5 58.75,47.5 60,47.5 31.875,48.077 55,48.375 70.125,48.375 50.625,48.75 61.25,48.75 75,49 54.125,49.625 1,50 50.625,50 52.75,50 62.5,50 94,50 50.625,51.25 52.75,51.25 63.75,51.25 73.375,52.25 50.625,52.5 52.75,52.5 65,52.5 74.375,53.25 13.75,53.75 21.25,53.75 50.625,53.75 52.75,53.75 66.25,53.75 7.75,54 75.375,54.125 27.5,54.25 1,55 50.625,55 52.75,55 67.5,55 76.25,55 94,55 37.5,56 76.5,56.125 50.625,56.25 52.75,56.25 68.75,56.25 76.5,57.25 50.625,57.5 52.75,57.5 70,57.875 53.875,58.75 76.5,58.75 50.875,58.875 1,59 7.25,59.25 54.75,59.375 70,59.625 51.75,59.875 39,60 76.5,60 55.75,60.5 57.5,60.5 59.375,60.5 61.25,60.5 63.125,60.5 65,60.5 66.875,60.5 68.75,60.5 52.625,60.875 21.25,61 76.5,61.25 13.75,61.5 35,61.75 53.5,61.75 76.5,62.25 94,62.375 54.375,62.5 75.75,63 55.375,63.25 74.5,63.25 56.75,63.5 57.875,63.5 59.25,63.5 1,64 73.5,64.25 59.375,64.375 74.875,64.625 76.25,64.625 77.875,64.625 79.625,64.625 81.5,64.625 83,64.625 50.625,65.375 52.5,65.5 54.375,65.5 84.875,65.5 59.625,66 60.625,66.25 73.75,66.25 74.875,66.25 76.25,66.25 77.875,66.25 79.625,66.25 81.5,66.25 83,66.25 61.75,66.5 71.5,66.75 72.625,66.75 49.25,66.875 55.75,66.875 78.25,67 79.125,67 80,67 70.5,67.25 84.25,67.375 61.75,67.5 69.5,68.25 49.25,68.5 55.75,68.5 61.25,68.5 74.625,68.875 75.375,68.875 76.375,68.875 77.125,68.875 35,69 73.5,69.25 69.5,69.5 30.25,69.75 61.25,69.75 78.25,69.875 79.125,69.875 80,69.875 81.125,69.875 82.25,69.875 83.5,69.875 84.625,69.875 85.875,69.875 25.75,70 49.25,70 55.75,70 70.75,70 72.25,70 73.5,70 61.25,71 49.25,71.5 55.75,71.5 67.875,71.5 61.25,72 16.25,72.5 27.125,72.5 67.875,72.625 50.625,72.75 52.5,72.75 54.375,72.75 61.25,73.25 24.125,73.375 25.375,73.375 41.875,73.375 55.25,73.5 56.5,73.5 31.375,73.75 54.25,73.75 67.875,73.75 7.25,74 42.875,74.125 57.5,74.25 32.375,74.5 53.25,74.5 58.5,74.5 59.5,74.5 60.5,74.5 18.25,75 28.75,75 65.5,75 66.625,75 67.875,75 68.875,75 70,75 6,75.5 52.5,76 53.5,76 64.5,76 70,76 1,77 63.75,77 53.5,77.25 70,77.25 63,78 54.25,78.25 55.25,78.25 57.5,78.25 58.5,78.25 59.5,78.25 60.5,78.25 61.5,78.25 70.5,78.5 24.125,78.625 72,78.75 73.5,78.75 75,78.75 77,78.75 78.5,78.75 80.25,78.75 81.625,78.75 83.125,78.75 84.625,78.75 56.25,79.125 59.5,79.5 54.75,79.75 21.25,80 36.25,80 67,80 76,80 57.5,80.5 58.5,80.5 51.75,81.75 8.25,84 12.5,84 17.5,84 22.5,84 27.5,84 32.5,84 37.5,84 42.5,84 47.5,84 52.5,84 57.5,84 62.5,84 67.5,84 72.5,84 77.5,84 82.5,84 86.5,84
  other v5: 16.75,55.45 18.25,55.45 15.45,56.75 16.75,56.75 18.25,56.75 19.55,56.75 15.45,58.25 16.75,58.25 18.25,58.25 19.55,58.25 16.75,59.55 18.25,59.55
  other v7: 3.5,3.5 91.5,3.5 3.5,81.5 91.5,81.5
  other v8: 20,8.7 20,9.8
GND-USB: J3.5 J3.6 J3.7 J3.8 J3.9 J3.10 J3.11 L3.1 | length 18.7
  Top Layer w1: J3.7@1.25,65.9 1.25,67.84 J3.8@1.45,68.04 ; J3.10@1.25,74.1 1.25,72.16 J3.9@1.45,71.96 ; J3.8@1.45,68.85 1.45,70.95 J3.9@1.5,71
  Mid-Layer 1 w1: J3.7@1.25,65.9 2.55,65.9 4.15,67.5 4.15,72.5 2.55,74.1 J3.10@1.25,74.1
I2C_ADDR0: R2.1 R3.2 U1.22 | length 5.8
  Top Layer w0.2: R2.1@50.5,32.25 51.5,32.25 51.987,32.737 U1.22@55.25,32.737
  Top Layer w0.254: R2.1@50.5,32.25 R3.2@50.5,33.125
I2C_ADDR1: R4.1 R5.2 U1.23 | length 5.9
  Top Layer w0.2: R4.1@50.5,31.375 51.75,31.375 52.477,32.102 U1.23@55.25,32.102
  Top Layer w0.254: R5.2@50.5,30.5 R4.1@50.5,31.375
I2S-SEL: D4.1 Q1.3 R54.2 U9.6 U10.6 U11.6 U13.6 | length 49.4
  Top Layer w0.25: 6.7,35 6.7,33.95 v1(6.25,33.5) 6.25,33 6.75,32.5 17.5,32.5 19,31 v1(21,31) 22.5,32.5 v1(28.75,32.5) ; v2(34.125,30.5) U11.6@35.3,30.5 ; v2(34.125,35.5) U10.6@35.3,35.5 ; v2(34.125,40.5) U9.6@35.3,40.5
  Mid-Layer 2 w0.25: v1(28.75,32.5) 30.5,34.25 32.875,34.25 v2(34.125,35.5)
  Bottom Layer w0.25: Q1.3@6.2,32.5 6.25,32.55 v1(6.25,33.5) ; v1(21,31) R54.2@21,31.75 21.01,31.75 21.51,32.25 U13.6@22.15,32.25 ; v2(34.125,30.5) v2(34.125,35.5) v2(34.125,40.5)
LRCLK-SPDIF: C62.1 R42.2 U11.2 | length 8.9
  Top Layer w0.25: C62.1@28,25.75 R42.2@28,26.75 30.625,26.75 31.25,27.375 31.25,30.625 31.625,31 U11.2@32.15,31 U11.2@32.225,31
MCLK: J5.2 U1.12 | length 14.6
  Top Layer w0.25: J5.2@42.5,40 42.5,38.75 43,38.25 48,38.25 48.625,38.875 48.838,39.088 U1.12@55.25,39.088
MCLK-SPDIF: C60.1 R39.2 U9.2 | length 21.6
  Top Layer w0.25: R39.2@20.75,29.25 C60.1@21.75,29.25 22.875,30.375 25.75,30.375 26.625,31.25 30,31.25 30.625,31.875 30.625,34.375 30,35 30,38.25 31.25,39.5 31.25,40.625 31.625,41 U9.2@32.15,41 U9.2@32.25,41
NetC10_2: C10.2 U1.6 | length 6.2
  Top Layer w0.254: C10.2@49.2,43.375 50,43.375 50.25,43.125 53.5,43.125 53.625,43 53.727,42.898 U1.6@55.237,42.898
NetC12_2: C12.2 U1.8 | length 8.3
  Top Layer w0.254: C12.2@47.75,42 48.375,41.375 48.663,41.375 48.665,41.373 49.735,41.373 49.744,41.381 ; 49.75,41.375 50.5,42.125 53.108,42.125 53.605,41.628 U1.8@55.237,41.628
NetC15_2: C15.2 U1.9 | length 2.9
  Top Layer w0.254: C15.2@52.5,41.25 53.125,41.25 53.382,40.992 U1.9@55.25,40.992
NetC16_2: C16.2 U1.10 | length 9.3
  Top Layer w0.254: v1(50.5,41.25) 51.125,41.25 C16.2@51.25,41.375 ; U1.10@55.25,40.357 56.483,40.357 56.75,40.625 v1(56.75,41.25)
  Bottom Layer w0.254: v1(50.5,41.25) v1(56.75,41.25)
NetC39_1: C39.1 R13.2 U2.103 | length 11.1
  Top Layer w0.25: v1(21.5,52.5) 22.5,52.5 25,50 v1(25,48.75)
  Bottom Layer w0.2: U2.103@21.3,49.8 21.3,50.8 21.5,51 v1(21.5,52.5)
  Bottom Layer w0.25: v1(25,48.75) 26.125,48.75 26.25,48.625 C39.1@26.25,47.375
NetC47_1: C47.1 R24.1 U2.45 | length 2.8
  Bottom Layer w0.2: R24.1@15,67 C47.1@15.875,67 16.1,66.775 U2.45@16.1,65.2
NetC48_1: C48.1 U6.5 | length 1.1
  Bottom Layer w0.2: U6.5@21.875,47.175 21.875,48.125 C48.1@22,48.25
NetC58_1: C58.1 R43.1 Y1.1 | length 3.5
  Top Layer w0.25: R43.1@24.7,21.875 26.425,21.875 Y1.1@26.525,21.975 26.675,22.125 C58.1@26.675,23.5
NetC59_1: C59.1 U12.7 Y1.3 | length 8.7
  Top Layer w0.25: U12.7@21.6,20.925 27.135,20.925 28.225,19.835 Y1.3@28.225,19.775 28.075,19.625 C59.1@28.075,18.25
NetC64_1: C64.1 S3.2 U14.3 | length 4.7
  Bottom Layer w0.2: S3.2@23.73,9.065 25.485,9.065 C64.1@25.55,9
  Bottom Layer w0.35: U14.3@20.95,9 21.625,9
  Bottom Layer w0.5: 21.625,9 23.665,9 S3.2@23.73,9.065
NetC68_1: C68.1 R50.2 U12.22 | length 2.5
  Top Layer w0.25: C68.1@14.25,21.75 R50.2@14.25,20.875 14.3,20.925 U12.22@15.9,20.925
NetC69_1: C69.1 R50.1 | length 0.9
  Top Layer w0.25: C69.1@12.375,20.875 R50.1@13.25,20.875
NetC71_2: C71.2 R51.1 U12.21 | length 10.3
  Top Layer w0.25: U12.21@15.9,21.575 17.125,21.575 17.375,21.325 17.375,18.625 18,18 18,15.625 18.625,15 R51.1@19.5,15 C71.2@20.5,15
NetC72_1: C72.1 U14.6 | length 0.8
  Bottom Layer w0.2: C72.1@18.2,9 U14.6@19.05,9
NetC92_2: C92.2 U16.4 | length 1.4
  Bottom Layer w0.25: C92.2@17.25,40.25 18.575,40.25 U16.4@18.625,40.3
NetC96_2: C96.2 U1.5 | length 6.4
  Top Layer w0.254: C96.2@49.25,44.625 49.75,44.625 50.75,43.625 53.839,43.625 53.931,43.533 U1.5@55.237,43.533
NetD1_1: D1.1 R7.1 | length 2.6
  Top Layer w0.254: D1.1@56.45,3.75 56.5,3.8 v1(56.5,5.25)
  Bottom Layer w0.254: R7.1@56.5,6.25 56.5,5.375 v1@56.625,5.25
NetD2_1: D2.1 R9.1 | length 2.5
  Top Layer w0.254: D2.1@50.2,3.75 50.25,3.8 v1(50.25,5.25)
  Bottom Layer w0.254: v1(50.25,5.25) R9.1@50.25,6.25
NetD3_1: D3.1 R20.2 | length 3.3
  Top Layer w0.2: D3.1@19.8,43.75 R20.2@23.05,43.75
NetD3_2: D3.2 U2.116 | length 8
  Top Layer w0.2: v1(15.625,46.875) 15.625,44.375 16.25,43.75 D3.2@17.7,43.75
  Bottom Layer w0.2: v1(15.625,46.875) 15.625,48.4 16.1,48.875 U2.116@16.1,49.8
NetD4_2: D4.2 R57.2 | length 2
  Top Layer w0.25: v1(5.125,36) 5.125,35.05 D4.2@5.175,35
  Bottom Layer w0.25: R57.2@5.125,35 v1(5.125,36)
NetD5_2: D5.2 R58.1 | length 3
  Top Layer w0.25: D5.2@46.8,81.75 R58.1@49.75,81.75
NetJ5_1: J5.1 R38.1 | length 2
  Top Layer w0.2: R38.1@38,40 J5.1@39.96,40
NetJ6_1: J6.1 R41.1 | length 2
  Top Layer w0.2: R41.1@38,35 J6.1@39.96,35
NetJ7_1: J7.1 R45.1 | length 2
  Top Layer w0.2: R45.1@38,30 J7.1@39.96,30
NetJ8_1: J8.1 R49.1 | length 21.4
  Bottom Layer w0.25: R49.1@22.125,29.5 22.125,27.875 25.875,24.125 32.5,24.125 33.375,25 J8.1@39.96,25
NetQ1_1: Q1.1 R48.1 | length 1.1
  Bottom Layer w0.25: R48.1@3.75,30.5 3.75,31.5 Q1.1@3.8,31.55
NetR14_1: R14.1 U2.63 | length 2
  Bottom Layer w0.2: R14.1@23.25,67.22 23.3,67.17 U2.63@23.3,65.2
NetR19_1: R19.1 U2.55 | length 1.8
  Bottom Layer w0.2: R19.1@20,67 20.1,66.9 U2.55@20.1,65.2
NetR21_1: R21.1 U2.64 | length 4.4
  Bottom Layer w0.2: U2.64@23.7,65.2 23.7,65.95 24,66.25 R21.1@27.22,66.25
NetR22_1: R22.1 U2.66 | length 3
  Bottom Layer w0.2: U2.66@25.2,63.3 26.05,63.3 26.25,63.5 26.25,64.03 R22.1@27.22,65
NetR23_1: R23.1 U2.13 | length 2
  Bottom Layer w0.2: R23.1@7.78,56.125 7.805,56.1 U2.13@9.8,56.1
NetR25_1: R25.1 U2.3 | length 2
  Bottom Layer w0.2: R25.1@7.78,52.125 7.805,52.1 U2.3@9.8,52.1
NetR27_2: R27.2 U2.48 | length 1.9
  Bottom Layer w0.2: U2.48@17.3,65.2 17.3,66.225 R27.2@17.875,66.8 ; R27.2@18.05,67.05 R27.2@18.125,67.05
NetR28_1: R28.1 U3.3 | length 1.2
  Bottom Layer w0.2: R28.1@13.03,46.125 13.725,46.125 U3.3@14,45.85
  Bottom Layer w0.25: U3.3@13.9,45.75 U3.3@14,45.85
NetR29_1: R29.1 U5.11 | length 16.7
  Bottom Layer w0.25: U5.11@11.25,37.05 11.25,35.75 11.75,35.25 14.125,35.25 15.375,36.5 R29.1@25.97,36.5
NetR30_1: R30.1 U5.9 | length 14.5
  Bottom Layer w0.2: U5.9@12.55,37.05 12.55,38.05 12.75,38.25 R30.1@25.97,38.25
NetR31_2: R31.2 R35.1 U6.3 | length 1.2
  Bottom Layer w0.2: R31.2@21.345,45.375 R35.1@21.345,46 21.375,46.03 U6.3@21.375,46.575
NetR32_2: R32.2 U6.4 U7.1 | length 3
  Bottom Layer w0.15: U7.1@19.65,47.225 19.65,47.945 R32.2@19.625,47.97 20.905,47.97 21.375,47.5 U6.4@21.375,47.175
NetR36_1: R36.1 U2.123 | length 2
  Bottom Layer w0.2: U2.123@13.3,49.8 13.3,48.95 R36.1@14.125,48.125
NetR37_1: R37.1 U8.3 | length 5
  Top Layer w0.25: U8.3@8.42,22.46 10.835,22.46 11.125,22.75 R37.1@13.25,22.75
NetR38_2: R38.2 U9.5 | length 1.6
  Top Layer w0.25: U9.5@35.35,40 R38.2@37,40
NetR39_1: R39.1 U12.4 | length 12.8
  Top Layer w0.25: R39.1@20.75,28.25 20,28.25 18.625,26.875 18.625,22.625 19.375,21.875 19.375,19.6 20,18.975 U12.4@21.6,18.975
NetR40_1: R40.1 U12.11 | length 8.7
  Top Layer w0.25: U12.11@21.6,23.525 23.525,23.525 25,25 25,27.25 26,28.25 R40.1@27,28.25
NetR41_2: R41.2 U10.5 | length 1.6
  Top Layer w0.25: U10.5@35.35,35 R41.2@37,35
NetR42_1: R42.1 U12.10 | length 8
  Top Layer w0.25: U12.10@21.6,22.875 24.125,22.875 26,24.75 26,26.5 26.25,26.75 R42.1@27,26.75
NetR43_2: R43.2 U12.8 | length 1.4
  Top Layer w0.25: U12.8@21.6,21.575 R43.2@23,21.575
NetR44_1: R44.1 U12.12 | length 3.6
  Top Layer w0.25: U12.12@21.6,24.175 23.05,24.175 23.75,24.875 R44.1@23.75,26
NetR45_2: R45.2 U11.5 | length 1.6
  Top Layer w0.25: U11.5@35.35,30 R45.2@37,30
NetR46_1: R46.1 U12.25 U12.26 | length 5.3
  Top Layer w0.25: U12.25@15.9,18.975 15.9,18.325 17,18.325 17.5,17.825 R46.1@17.5,15
NetR47_1: R47.1 U12.28 | length 1.8
  Top Layer w0.25: v1(15.75,16.125) 15.75,16.975 U12.28@15.8,17.025
  Bottom Layer w0.25: v1(15.75,16.125) R47.1@15.75,17
NetR47_2: R47.2 R48.2 U12.27 | length 25.2
  Top Layer w0.25: v1(14,17) 14.675,17.675 U12.27@15.8,17.675
  Bottom Layer w0.25: R48.2@3.75,29.5 3.75,18.75 6.25,16.25 13.25,16.25 v1(14,17) R47.2@14.75,17
NetR49_2: R49.2 U13.5 | length 1.3
  Bottom Layer w0.25: R49.2@22.125,30.5 22.15,30.525 U13.5@22.15,31.75
NetR52_1: R52.1 R53.2 U12.13 | length 11.4
  Top Layer w0.25: R52.1@13.75,28.875 R53.2@15,28.875 v2(15,27.5) ; v2(20,24.375) 20.45,24.825 U12.13@21.6,24.825
  Bottom Layer w0.25: v2(15,27.5) 15,26.25 16.875,24.375 v2@19.875,24.375 ; v2@19.937,24.438 v2(20,24.375)
NetR55_1: R55.1 R56.2 U12.14 | length 8.7
  Top Layer w0.25: R56.2@16.25,28.875 R55.1@17.5,28.875 ; v2(20,25.875) 20.4,25.475 U12.14@21.6,25.475
  Top Layer w0.254: R56.2@16.25,28.875 16.25,27.75 v2(16.5,27.5)
  Bottom Layer w0.25: v2(16.5,27.5) 18.375,27.5 v2(20,25.875)
NetR59_1: R59.1 R61.2 U17.5 | length 2.9
  Bottom Layer w0.25: R61.2@29.5,72.5 R59.1@30.675,72.5 ; U17.5@30.125,74.05 30.125,73.625 30.5,73.25 30.5,72.625 R59.1@30.625,72.5
NetU4_7: U4.7 U5.1 | length 1.6
  Bottom Layer w0.15: U5.1@9.3,42.95 9.325,42.975 U4.7@9.325,44.55
OUT1+: C112.1 C113.2 J1.2 L11.2
OUT1-: C114.1 C115.2 J1.1 L12.2
OUT1M: C107.2 L12.1 U1.32 | length 1.1
  Bottom Layer w0.25: C107.2@65.325,29.875 v4(66.375,29.875)
  other v4: 67.125,29.25 67.875,29.875
OUT1P: C106.2 L11.1 U1.34 | length 1.1
  Bottom Layer w0.25: C106.2@65.325,32.375 v4(66.375,32.375)
  other v4: 67.375,31.375 67.375,32.375
OUT2+: C108.1 C109.2 J1.4 L9.2 | length 2
  Bottom Layer w0.5: C109.2@89,35.75 89.25,35.75 J1.4@91,35.75
OUT2-: C110.1 C111.2 J1.3 L10.2 | length 2.2
  Bottom Layer w0.5: C111.2@89,32.625 89.375,32.25 J1.3@91,32.25
OUT2M: C105.2 L10.1 U1.38 | length 1.2
  Bottom Layer w0.25: C105.2@65.325,34.375 v2(66.5,34.375)
OUT2P: C104.2 L9.1 U1.40 | length 1.6
  Bottom Layer w0.25: C104.2@65.325,36.25 65.7,35.875 v2(66.75,35.875)
OUT3+: C99.1 C100.2 J1.6 L7.2 | length 2.2
  Bottom Layer w0.5: C100.2@89,42.375 89.375,42.75 J1.6@91,42.75
OUT3-: C101.1 C102.2 J1.5 L8.2 | length 2
  Bottom Layer w0.5: C102.2@89,39.25 89.25,39.25 J1.5@91,39.25
OUT3M: C98.2 L8.1 U1.45 | length 1.6
  Bottom Layer w0.25: C98.2@65.325,38.75 65.7,39.125 v2(66.75,39.125)
OUT3P: C97.2 L7.1 U1.47 | length 1.2
  Bottom Layer w0.25: C97.2@65.325,40.625 v2(66.5,40.625)
OUT4+: C7.1 C8.2 J1.8 L1.2
OUT4-: C13.1 C14.2 J1.7 L2.2
OUT4M: C9.2 L2.1 U1.51 | length 1.1
  Bottom Layer w0.25: C9.2@65.325,42.625 v4(66.375,42.625)
  other v4: 67.375,42.625 67.375,43.625
OUT4P: C6.2 L1.1 U1.53 | length 1.1
  Bottom Layer w0.25: C6.2@65.325,45.125 v4(66.375,45.125)
  other v4: 67.875,45.125 67.125,45.75
PVDD: C2.1 C3.2 C4.1 C5.2 C81.1 C82.2 C93.2 C94.1 C95.2 J13.2 L4.2 L5.1 U1.2 U1.29 U1.30 U1.42 U1.43 U1.55 U1.56 | length 5.5
  Top Layer w0.25: C5.2@52.425,47.25 C4.1@52.425,48.55
  Top Layer w0.254: C5.2@52.5,47.25 52.509,47.241 52.509,46.634 52.767,46.375 53.375,46.375 53.75,46 53.75,45.5 53.835,45.415 U1.2@55.25,45.415
  other v1: 73.375,59.625 74.5,59.625 75.625,59.625 73.375,60.75 75.625,60.75 73.375,61.875 74.5,61.875 75.625,61.875
  other v2: 56.875,45 56.875,45.875
  other v3: 63.875,67.5 65.125,67.5 66.375,67.5 67.625,67.5 63.875,68.75 65.125,68.75 66.375,68.75 67.625,68.75 63.875,70 65.125,70 66.375,70 67.625,70
  other v4: 64.25,27.125 65.25,27.125 64.25,28.125 65.25,28.125 60.625,37 61.75,37 60.625,38 61.75,38 64.25,46.875 65.25,46.875 64.25,47.875 65.25,47.875
PVDD-VR: C83.1 C84.2 L5.2 U15.1
RXIN: C57.1 R37.2 U12.20 | length 2.7
  Top Layer w0.25: C57.1@14.25,23.625 R37.2@14.25,22.75 14.26,22.75 14.785,22.225 U12.20@15.9,22.225
SCL: J14.1 R11.2 U1.20 U2.37 U5.12 | length 119.2
  Top Layer w0.25: v1(4.375,40.5) 3.125,41.75 3.125,62.875 4,63.75 8.125,63.75 v1(10,65.625) ; v1(10.625,35.625) 11.25,35 25,35 26.25,33.75 v1(28.125,33.75) ; U1.20@55.25,34.007 56.257,34.007 v1(56.75,34.5)
  Bottom Layer w0.2: v1(10,65.625) 10.875,66.5 12.5,66.5 12.9,66.1 U2.37@12.9,65.2
  Bottom Layer w0.25: v1(4.375,40.5) R11.2@6.875,40.5 9.5,40.5 10.6,39.4 U5.12@10.6,37.15 10.6,37.05 10.625,37.025 v1(10.625,35.625) ; v1(28.125,33.75) 28.125,30 29.375,28.75 34.375,28.75 35.875,30.25 35.875,31.375 36.421,31.921 36.421,32.49 36.871,32.94 36.871,33.121 36.875,33.125 36.875,35.625 38.125,36.875 ; J14.1@42.5,47.545 40.42,47.545 38.125,45.25 38.125,36.875 ; v1(56.75,34.5) 54.375,36.875 38.125,36.875
SCLK: J6.2 U1.13 | length 14.8
  Top Layer w0.25: J6.2@42.5,35 42.5,36.125 43.125,36.75 48.875,36.75 50.578,38.453 U1.13@55.25,38.453
SCLK-SPDIF: C61.1 R40.2 U10.2 | length 11.8
  Top Layer w0.25: C61.1@28,29.25 R40.2@28,28.25 29.5,28.25 30,28.75 v1(30,30) ; v1(31.25,35.5) 31.25,35.875 31.375,36 U10.2@32.15,36
  Bottom Layer w0.25: v1(30,30) 30.625,30.625 30.625,34.875 v1(31.25,35.5)
SDA: J14.3 R12.2 U1.21 U2.38 U5.13 | length 147.2
  Top Layer w0.25: v1(4.375,38.75) 2,41.125 2,63.25 3.75,65 8.125,65 v1(9.375,66.25) ; v1(9.375,38.75) 10.625,37.5 24.375,37.5 v1(26.875,35) ; U1.21@55.25,33.372 56.748,33.372 v1(56.75,33.375)
  Bottom Layer w0.2: v1(9.375,66.25) 10,66.25 10.75,67 12.625,67 13.3,66.325 U2.38@13.3,65.2
  Bottom Layer w0.25: v1(4.375,38.75) R12.2@6.875,38.75 v1(9.375,38.75) 9.95,38.175 U5.13@9.95,37.15 U5.13@9.95,37.05 ; v1(26.875,35) 26.875,29.375 28.75,27.5 35,27.5 37.5,30 37.5,31.25 39.375,33.125 46.875,33.125 49.375,35.625 53.125,35.625 55.375,33.375 v1(56.75,33.375) ; v1@27,35 28.319,35 29.375,33.944 29.375,29.806 29.76,29.421 31.352,29.421 31.885,29.954 33.673,29.954 33.833,29.794 34.417,29.794 35.425,30.802 35.425,31.561 35.971,32.107 35.971,32.676 36.421,33.126 36.421,37.49 36.671,37.74 36.671,42.365 37.675,43.369 37.675,47.8 J14.3@42.5,52.625
SDIN: J2.1 J8.2 U1.15 | length 27.7
  Top Layer w0.25: J2.1@39.92,20.25 39.92,21.42 42.5,24 J8.2@42.5,24.875 ; J2.1@39.96,20 J2.1@39.96,20.25 ; J8.2@42.5,25 42.5,26.625 43.375,27.5 46.25,27.5 47.5,28.75 47.5,33.75 48.25,34.5 49.375,34.5 51.75,36.875 51.875,36.875 ; 51.875,36.95 51.875,37.125 51.932,37.183 U1.15@55.25,37.183
SDIN2: J2.2 U1.16 | length 26.6
  Top Layer w0.25: v1(50.875,34.625) 51.8,35.55 51.875,35.55 ; 51.875,35.625 52,35.625 52.922,36.547 U1.16@55.25,36.547
  Bottom Layer w0.25: J2.2@42.5,20 42.5,21.5 43.125,22.125 48.875,22.125 50.875,24.125 v1(50.875,34.625)
SDOUT-SPDIF: C63.1 R44.2 U13.2 | length 7.9
  Top Layer w0.25: C63.1@22.75,27 R44.2@23.75,27 v1(23.75,28.75)
  Bottom Layer w0.25: v1(23.75,28.75) 23.75,32 24.5,32.75 U13.2@25.35,32.75
SW: L6.1 U17.3
USB-DM: J3.2 U2.47 | length 19.2
  Top Layer w0.25: J3.2@4.3,70.65 9.15,70.65 10.375,71.875 15,71.875 v1(17.5,69.375)
  Bottom Layer w0.2: U2.47@16.9,65.2 16.9,68.775 v1(17.5,69.375)
USB-DP: J3.3 U2.46 | length 16.1
  Top Layer w0.25: J3.3@4.3,70 15,70 v1(15.625,69.375)
  Bottom Layer w0.2: v1(15.625,69.375) 16.5,68.5 U2.46@16.5,65.2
